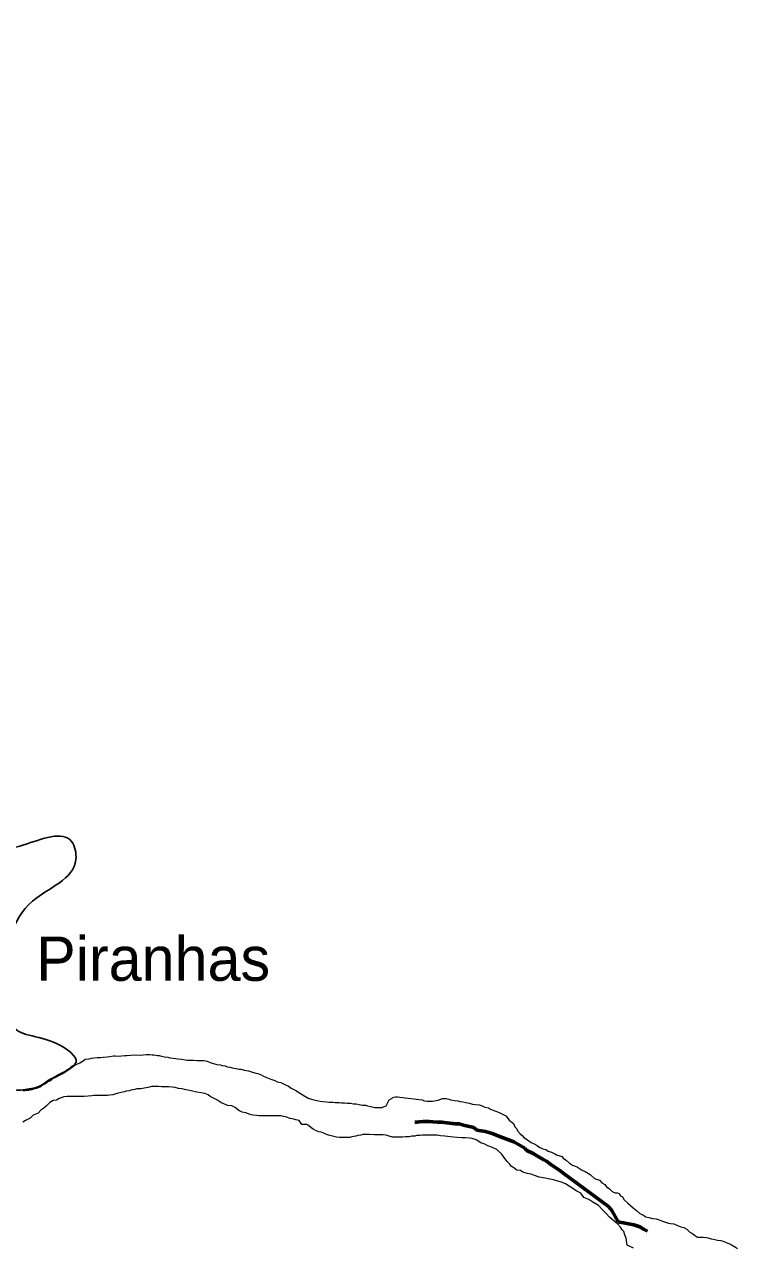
# Model space of a CAD drawing. Extents: x 553962 to 842807, y 8883888 to 9032388.
# Drawn here: x 636281 to 644560, y 8933785 to 8947589 of the extents above; entities that cross this region are included whole.
import ezdxf

# ---------------------------------------------------------------- set-up
doc = ezdxf.new("R2010")
doc.units = 0
doc.header["$LTSCALE"] = 200
doc.linetypes.add('LONG_DASH_SHORT_DASH', pattern=[9.9, 6, -1.2, 1.5, -1.2])
for name, color, linetype, lineweight in [('21', 7, 'Continuous', 25), ('25', 7, 'Continuous', 13), ('7', 7, 'LONG_DASH_SHORT_DASH', 60), ('9', 7, 'Continuous', 90)]:
    doc.layers.add(name, color=color, linetype=linetype, lineweight=lineweight)
doc.layers.add('41', color=7, linetype='Continuous')

msp = doc.modelspace()

# ---------------------------------------------------------------- linework, layer by layer
at = {"layer": '21'}
msp.add_spline([(635677.5, 8935542.3), (635110.6, 8935620.5), (634836.9, 8935855.3), (634709.8, 8936099.8), (634846.6, 8936275.8), (634973.7, 8936735.4), (635032.4, 8937263.6), (634739.1, 8937449.4), (634426.3, 8937517.8), (634700, 8937928.6), (634700, 8938261.1), (634533.8, 8938671.9), (634641.4, 8938906.6), (634768.4, 8938867.5), (634866.2, 8938740.3), (635130.1, 8938750.1), (635188.8, 8938564.3), (635325.6, 8938329.6), (635609.1, 8938251.3), (636273.8, 8938329.6), (636811.4, 8938368.7), (636860.3, 8938163.3), (636371.5, 8937693.9), (636136.9, 8937312.5), (636127.2, 8936784.3), (636156.5, 8936275.8), (636694.1, 8936060.6), (636850.5, 8935855.3), (636821.3, 8935831.4), (636756.6, 8935782.4), (636679.7, 8935742.2), (636611.5, 8935703.8), (636571.3, 8935684.5), (636504.8, 8935639.1), (636420.9, 8935593.6), (636337, 8935576.1), (636239.1, 8935562.1), (636151.7, 8935569.1), (636071.2, 8935593.6), (635990.8, 8935618.1), (635878.9, 8935632.1), (635826.5, 8935633.8), (635795, 8935628.6), (635758.3, 8935612.8), (635712.8, 8935584.8), (635680.9, 8935555.9), (635677.5, 8935542.3)], degree=3, dxfattribs=at)
at = {"layer": '25'}
for points in [[(636263.5, 8935558.1), (636283.5, 8935557.9), (636303.5, 8935560.3), (636326, 8935562.7), (636346.1, 8935565), (636366.1, 8935569.9), (636398.7, 8935579.7), (636418.7, 8935582.1), (636456.4, 8935599.4), (636479, 8935616.7), (636519.2, 8935636.5), (636539.3, 8935653.9), (636579.5, 8935671.2), (636602.1, 8935691), (636642.3, 8935710.8), (636675, 8935730.6), (636712.6, 8935747.9), (636737.7, 8935762.7), (636770.4, 8935785.1), (636793.1, 8935802.4), (636835.8, 8935834.7), (636863.5, 8935852), (636906.1, 8935869.3), (636941.3, 8935891.6), (636964, 8935908.9), (637009, 8935916.2), (637036.6, 8935923.5), (637099.2, 8935928.1), (637136.7, 8935930.3), (637169.2, 8935935.1), (637214.3, 8935937.3), (637241.8, 8935942.2), (637284.4, 8935946.9), (637304.4, 8935946.8), (637351.9, 8935946.4), (637374.4, 8935948.8), (637412, 8935951.1), (637437, 8935953.4), (637479.5, 8935955.6), (637524.6, 8935960.3), (637584.6, 8935954.9), (637652.2, 8935962), (637672.2, 8935961.8), (637694.7, 8935961.7), (637719.7, 8935961.5), (637742.2, 8935958.9), (637777.1, 8935953.6), (637799.7, 8935953.5), (637824.6, 8935945.8), (637859.6, 8935938.1), (637897, 8935932.8), (637922, 8935927.6), (637959.5, 8935922.4), (637989.5, 8935917.2), (638012, 8935914.5)], [(638012, 8935914.5), (638051.9, 8935909.3), (638091.9, 8935904), (638116.9, 8935901.3), (638154.4, 8935901.1), (638186.9, 8935898.3), (638226.9, 8935895.6), (638259.4, 8935895.4), (638281.9, 8935895.2), (638301.9, 8935895.1), (638341.9, 8935887.3), (638376.8, 8935874.6), (638414.2, 8935861.8), (638449.2, 8935851.6), (638486.6, 8935846.3), (638509.1, 8935841.1), (638544.1, 8935835.9), (638566.5, 8935825.7), (638599, 8935820.5), (638621.5, 8935812.9), (638663.9, 8935805.1), (638701.4, 8935799.8), (638721.4, 8935799.7), (638761.3, 8935786.9), (638808.8, 8935779.1), (638851.2, 8935763.8), (638891.1, 8935753.5), (638913.6, 8935750.8), (638951, 8935733.1), (638978.4, 8935717.9), (639020.8, 8935700.1), (639058.2, 8935684.8), (639103.1, 8935669.5), (639130.5, 8935656.8), (639170.4, 8935646.5), (639195.4, 8935636.3), (639232.7, 8935618.6), (639260.2, 8935605.8), (639290, 8935583.1), (639327.4, 8935565.3), (639349.8, 8935555.2), (639374.7, 8935535), (639412, 8935512.2), (639444.4, 8935494.5), (639481.7, 8935471.7), (639519.2, 8935458.9), (639544.1, 8935451.3), (639576.6, 8935443.5), (639614, 8935438.3), (639646.5, 8935433.1), (639686.5, 8935427.8), (639719, 8935425.1), (639739, 8935424.9), (639761.5, 8935424.8), (639784, 8935422.1), (639814, 8935421.9), (639834, 8935421.8), (639856.5, 8935419.1), (639889, 8935416.4), (639921.5, 8935413.7), (639956.5, 8935413.5), (639991.5, 8935408.2), (640021.5, 8935405.5), (640053.9, 8935400.3), (640093.9, 8935392.5), (640126.4, 8935389.8), (640148.9, 8935384.7), (640183.8, 8935376.9), (640233.7, 8935364.2), (640316.3, 8935366), (640339.2, 8935375.1), (640361.5, 8935385.8), (640394.5, 8935450.6), (640447.2, 8935480.3), (640467.3, 8935485.2), (640487.3, 8935485.1), (640514.8, 8935482.4), (640549.8, 8935479.7), (640572.2, 8935474.5), (640607.2, 8935471.8), (640639.7, 8935466.5), (640677.2, 8935463.8), (640699.7, 8935461.1), (640732.2, 8935455.9), (640767.1, 8935450.7), (640789.6, 8935440.5), (640822, 8935435.3), (640842.1, 8935435.2), (640864.6, 8935435), (640884.6, 8935434.9), (640947.2, 8935447), (640994.9, 8935466.7), (641014.9, 8935466.6), (641037.4, 8935466.4), (641067.3, 8935461.2), (641089.8, 8935453.6), (641132.3, 8935445.8), (641167.2, 8935440.5), (641189.7, 8935432.8), (641224.7, 8935427.6), (641259.6, 8935419.9)], [(638992.5, 8935272.2), (638970, 8935272.3), (638925, 8935272.6), (638897.5, 8935275.3), (638855, 8935278.1), (638825, 8935285.8), (638777.6, 8935303.6), (638737.7, 8935311.4), (638700.3, 8935331.7), (638658.1, 8935364.5), (638618.2, 8935382.3), (638573.2, 8935387.6), (638535.8, 8935402.8), (638495.9, 8935423.1), (638451.1, 8935451), (638413.8, 8935471.2), (638376.4, 8935489), (638351.5, 8935506.7), (638314.1, 8935522), (638274.1, 8935529.8), (638224.2, 8935537.6), (638161.8, 8935553), (638086.8, 8935568.6), (638059.4, 8935576.2), (638019.4, 8935581.5), (637982, 8935591.8), (637947, 8935594.5), (637907, 8935599.8), (637884.5, 8935599.9), (637847, 8935600.2), (637827, 8935600.3), (637792, 8935600.5), (637754.5, 8935600.8), (637714.4, 8935601.1), (637691.9, 8935596.2), (637654.3, 8935588.9), (637631.8, 8935584.1), (637591.7, 8935576.8), (637549.2, 8935574.6), (637524.1, 8935567.3), (637481.5, 8935560), (637461.5, 8935552.7), (637426.4, 8935547.9), (637406.4, 8935543), (637371.3, 8935535.7), (637336.2, 8935528.4), (637298.6, 8935516.2), (637278.5, 8935508.8), (637238.5, 8935504.1), (637215.9, 8935499.2), (637180.9, 8935499.4), (637135.9, 8935499.7), (637105.9, 8935499.9), (637063.4, 8935500.2), (637040.8, 8935497.9), (637000.8, 8935493.1), (636955.8, 8935490.9), (636930.8, 8935491.1), (636890.7, 8935488.8), (636868.2, 8935489), (636830.7, 8935489.2), (636810.7, 8935489.4), (636780.7, 8935489.6), (636760.7, 8935489.7), (636725.6, 8935484.9), (636693, 8935475.1), (636673, 8935467.8), (636640.3, 8935447.9), (636605.2, 8935443.2), (636567.6, 8935420.9), (636524.7, 8935381.1), (636499.6, 8935358.7), (636466.9, 8935336.4), (636436.6, 8935301.6), (636416.5, 8935294.2), (636378.9, 8935276.9), (636343.6, 8935244.6), (636323.5, 8935234.7), (636293.4, 8935219.9), (636260.8, 8935200.1)], [(641259.6, 8935419.9), (641294.6, 8935414.6), (641334.5, 8935404.4), (641369.5, 8935399.1), (641409.5, 8935393.8), (641441.9, 8935383.6), (641474.3, 8935368.4), (641514.3, 8935363.1), (641536.7, 8935345.4), (641574.1, 8935330.2), (641596.6, 8935325), (641636.4, 8935307.2), (641673.8, 8935289.5), (641708.7, 8935271.7), (641748.3, 8935223.9), (641798.1, 8935183.5), (641812.8, 8935148.3), (641832.6, 8935125.7), (641842.5, 8935100.6), (641872.2, 8935067.8), (641894.6, 8935047.7), (641916.9, 8935022.5), (641954.2, 8935002.2), (641994, 8934971.9), (642028.9, 8934954.1), (642063.8, 8934936.4), (642086.2, 8934918.7), (642126, 8934898.4), (642161, 8934890.7), (642188.4, 8934873), (642225.8, 8934860.2), (642260.7, 8934842.4), (642283.1, 8934832.3), (642318, 8934819.5), (642340.5, 8934811.9), (642357.8, 8934791.7), (642395.2, 8934769), (642427.4, 8934736.2), (642462.3, 8934715.9), (642484.8, 8934708.3), (642517.1, 8934690.5), (642539.5, 8934675.4), (642561.9, 8934660.2), (642604.3, 8934642.4), (642661.6, 8934609.5), (642711.2, 8934564.1), (642766.1, 8934543.7), (642790.9, 8934513.5), (642825.8, 8934495.7), (642845.6, 8934470.6), (642875.5, 8934450.3), (642907.7, 8934417.6), (642942.6, 8934402.3), (642965.1, 8934402.2), (642987.6, 8934394.5), (643004.9, 8934366.9), (643027.3, 8934356.7), (643044.6, 8934324), (643084.3, 8934286.2), (643146.4, 8934233.2), (643183.7, 8934202.9), (643221, 8934167.7), (643253.4, 8934152.4), (643288.2, 8934132.2), (643323.2, 8934124.4), (643363.1, 8934114.1), (643405.6, 8934108.8), (643440.5, 8934096.1), (643477.9, 8934083.3), (643500.4, 8934075.7), (643542.8, 8934060.4), (643567.8, 8934055.2), (643602.8, 8934052.5), (643647.6, 8934034.7), (643685, 8934019.4), (643717.5, 8934009.2), (643749.9, 8933993.9), (643784.6, 8933958.6), (643814.5, 8933943.4), (643836.9, 8933925.7), (643871.7, 8933903), (643899.2, 8933902.8), (643936.7, 8933900.1), (643971.7, 8933897.3), (644004.2, 8933892.1), (644026.7, 8933884.4), (644066.6, 8933876.7), (644096.6, 8933868.9), (644136.6, 8933863.7), (644161.5, 8933856), (644196.4, 8933843.2), (644226.3, 8933830.5), (644263.7, 8933810.3), (644301.1, 8933790), (644323.4, 8933772.3)], [(642690, 8934297.2), (642645.2, 8934327.5), (642587.9, 8934347.9), (642556.4, 8934400.2), (642504.8, 8934424.3), (642466.9, 8934451.8), (642425.6, 8934475.9), (642384.3, 8934503.4), (642339.5, 8934524.1), (642294.8, 8934534.4), (642294.8, 8934534.4), (642246.6, 8934548.2), (642188.1, 8934561.9), (642151.8, 8934566.1), (642086.9, 8934579), (642032, 8934596.9), (641994.6, 8934612.2), (641952.2, 8934620), (641902.2, 8934635.3), (641874.9, 8934653.1), (641834.9, 8934658.3), (641800.1, 8934686.1), (641770.2, 8934701.3), (641755.4, 8934726.4), (641723.1, 8934756.7), (641698.3, 8934789.4), (641681, 8934817.1), (641663.7, 8934837.2), (641628.9, 8934872.5), (641609.1, 8934892.6), (641558.1, 8934912.8), (641506.5, 8934933.5), (641473.6, 8934950.3), (641426.3, 8934968.1), (641376.5, 8935001), (641329.1, 8935016.3), (641301.6, 8935019), (641254.1, 8935021.8), (641209.1, 8935024.7), (641159.1, 8935027.5), (641081.6, 8935035.5), (641021.6, 8935040.9), (640971.7, 8935046.2), (640936.7, 8935051.5), (640899.2, 8935054.2), (640864.2, 8935054.5), (640841.7, 8935054.6), (640806.6, 8935054.8), (640769.1, 8935052.6), (640744.1, 8935050.3), (640704, 8935048), (640684, 8935043.2), (640649, 8935040.9), (640621.4, 8935036.1), (640578.9, 8935033.8), (640543.8, 8935031.6), (640498.8, 8935031.8), (640471.3, 8935032), (640451.3, 8935032.2), (640431.3, 8935032.3), (640393.9, 8935042.6), (640358.9, 8935052.8), (640326.5, 8935058), (640229.1, 8935058.3), (640168.9, 8935061.6), (640141.4, 8935061.8), (640098.9, 8935059.5), (640076.3, 8935052.2), (640041.2, 8935047.4), (640016.2, 8935040.1), (639971.1, 8935032.8), (639951.1, 8935028), (639898.5, 8935025.8), (639856, 8935026.1), (639833.5, 8935026.2), (639801, 8935029), (639768.6, 8935039.2), (639738.6, 8935044.4), (639708.7, 8935054.6), (639686.2, 8935062.3), (639663.8, 8935072.4), (639628.9, 8935085.2), (639601.4, 8935090.4), (639564, 8935105.6), (639536.6, 8935120.8), (639511.7, 8935141), (639489.3, 8935158.7), (639464.5, 8935173.9), (639409.4, 8935171.8), (639379.8, 8935217), (639342.3, 8935227.3), (639317.4, 8935234.9), (639274.9, 8935242.7), (639240, 8935255.5), (639202.5, 8935263.2), (639177.6, 8935270.9), (639125.1, 8935271.3), (639090, 8935271.5), (639050, 8935271.8), (639030, 8935271.9), (638992.5, 8935272.2)], [(643148, 8933777.6), (643078.2, 8933813.1), (643066.3, 8933890.8), (643056.5, 8933918.4), (643046.7, 8933941), (643039.3, 8933966.1), (643022, 8933986.2), (643004.7, 8934016.4), (642970, 8934051.7), (642947.6, 8934071.8), (642910.3, 8934099.6), (642880.5, 8934127.3), (642842.1, 8934169.7), (642842.1, 8934169.7), (642804.3, 8934207.6), (642755, 8934260.3), (642734.8, 8934269.3), (642690, 8934297.2)]]:
    msp.add_lwpolyline(points, dxfattribs=at)
at = {"layer": '7'}
for points in [[(641349.5, 8935138.5), (641279.6, 8935153.8), (641232.2, 8935166.6), (641182.2, 8935179.4), (641137.2, 8935182.1), (641014.8, 8935197.8), (640987.4, 8935200.4), (640937.4, 8935200.7), (640887.4, 8935203.5), (640847.4, 8935206.2), (640824.9, 8935206.3), (640794.9, 8935206.5), (640772.4, 8935206.6), (640732.4, 8935204.3), (640707.4, 8935199.4), (640683.2, 8935198.4)], [(643306.9, 8933971.4), (643271.7, 8933987.2), (643222, 8934017.5), (643154.6, 8934040.4), (642977.3, 8934076.3), (642905.7, 8934204.3), (642868.5, 8934249.6), (642368.5, 8934617.6), (642318.7, 8934652.9), (642216.7, 8934723.5), (642166.9, 8934758.8), (642137, 8934776.5), (642047.4, 8934827), (642025, 8934842.1), (641937.8, 8934885.1), (641922.9, 8934907.7), (641800.9, 8934978.4), (641648.8, 8935034.3), (641556.5, 8935072.3), (641479.2, 8935095.2), (641381.8, 8935110.8), (641349.5, 8935138.5)]]:
    msp.add_lwpolyline(points, dxfattribs=at)
at = {"layer": '9'}
msp.add_spline([(637260.6, 8972975.8), (641524.5, 8971056.2), (652526.1, 8965412.7), (653164.3, 8965062.8), (670790.5, 8953770.1), (686194, 8943929.9), (696283.3, 8937647.1)], degree=3, dxfattribs=at)

# ---------------------------------------------------------------- texts
at = {"layer": '41'}
msp.add_text('Piranhas', height=500, dxfattribs=at).set_placement((636412.8, 8936794.9))

doc.saveas('drawing.dxf')
